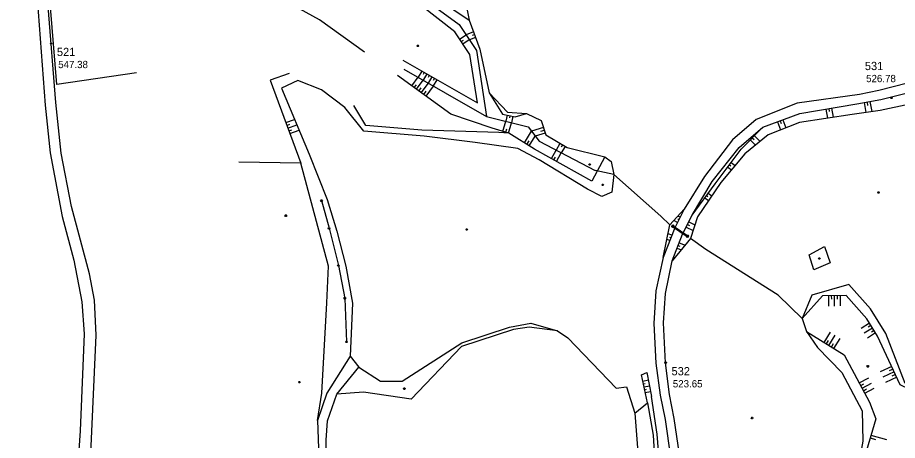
# Model space of a CAD drawing. Extents: x -664960 to -662754, y -993849 to -991145.
# Drawn here: x -664136.9 to -663773.7, y -992233.7 to -992059.4 of the extents above; entities that cross this region are included whole.
import ezdxf

# ---------------------------------------------------------------- set-up
doc = ezdxf.new("R2010")
doc.units = 0
for name, color, linetype in [('Vrstva 1', 7, 'Continuous'), ('Vrstva 12', 7, 'Continuous'), ('Vrstva 13', 7, 'Continuous'), ('Vrstva 24', 7, 'Continuous'), ('Vrstva 27', 7, 'Continuous'), ('Vrstva 28', 7, 'Continuous'), ('Vrstva 63', 7, 'Continuous'), ('Vrstva 8', 7, 'Continuous')]:
    doc.layers.add(name, color=color, linetype=linetype)

msp = doc.modelspace()

# ---------------------------------------------------------------- linework, layer by layer
at = {"layer": 'Vrstva 12'}
msp.add_lwpolyline([(-664087.76, -992082.088), (-664120.622, -992086.914), (-664123.342, -992055.125), (-664091.387, -992050.694)], dxfattribs=at)
at = {"layer": 'Vrstva 13'}
for points in [[(-663971.458, -992070.684), (-663971.278, -992070.984), (-663971.458, -992071.284), (-663971.818, -992071.284), (-663971.998, -992070.984), (-663971.818, -992070.684), (-663971.458, -992070.684)], [(-663900.569, -992119.625), (-663900.389, -992119.925), (-663900.569, -992120.225), (-663900.929, -992120.225), (-663901.109, -992119.925), (-663900.929, -992119.625), (-663900.569, -992119.625)], [(-663895.117, -992127.985), (-663894.937, -992128.285), (-663895.117, -992128.585), (-663895.477, -992128.585), (-663895.657, -992128.285), (-663895.477, -992127.985), (-663895.117, -992127.985)], [(-663781.28, -992131.148), (-663781.1, -992131.448), (-663781.28, -992131.748), (-663781.64, -992131.748), (-663781.82, -992131.448), (-663781.64, -992131.148), (-663781.28, -992131.148)], [(-664025.982, -992140.708), (-664025.802, -992141.008), (-664025.982, -992141.308), (-664026.342, -992141.308), (-664026.522, -992141.008), (-664026.342, -992140.708), (-664025.982, -992140.708)], [(-663951.26, -992146.389), (-663951.08, -992146.689), (-663951.26, -992146.989), (-663951.62, -992146.989), (-663951.8, -992146.689), (-663951.62, -992146.389), (-663951.26, -992146.389)], [(-663785.698, -992202.87), (-663785.518, -992203.17), (-663785.698, -992203.47), (-663786.058, -992203.47), (-663786.238, -992203.17), (-663786.058, -992202.87), (-663785.698, -992202.87)], [(-664020.348, -992209.413), (-664020.168, -992209.713), (-664020.348, -992210.013), (-664020.708, -992210.013), (-664020.888, -992209.713), (-664020.708, -992209.413), (-664020.348, -992209.413)], [(-663833.462, -992224.146), (-663833.282, -992224.446), (-663833.462, -992224.746), (-663833.822, -992224.746), (-663834.002, -992224.446), (-663833.822, -992224.146), (-663833.462, -992224.146)]]:
    msp.add_lwpolyline(points, dxfattribs=at)
at = {"layer": 'Vrstva 24'}
for p, q in [((-663866.501, -992145.522), (-663860.402, -992149.633)), ((-663866.278, -992145.19), (-663860.179, -992149.301))]:
    msp.add_line(p, q, dxfattribs=at)
for points in [[(-663866.185, -992145.374), (-663866.203, -992145.723), (-663866.52, -992145.871), (-663866.818, -992145.67), (-663866.8, -992145.321), (-663866.483, -992145.173), (-663866.185, -992145.374)], [(-663866.129, -992145.507), (-663866.478, -992145.489), (-663866.627, -992145.173), (-663866.427, -992144.874), (-663866.078, -992144.891), (-663865.928, -992145.208), (-663866.129, -992145.507)], [(-663860.086, -992149.484), (-663860.104, -992149.834), (-663860.421, -992149.982), (-663860.719, -992149.781), (-663860.701, -992149.431), (-663860.384, -992149.283), (-663860.086, -992149.484)], [(-663860.328, -992148.984), (-663859.979, -992149.002), (-663859.829, -992149.318), (-663860.03, -992149.617), (-663860.379, -992149.6), (-663860.528, -992149.284), (-663860.328, -992148.984)]]:
    msp.add_lwpolyline(points, dxfattribs=at)
at = {"layer": 'Vrstva 27'}
for points in [[(-664136.56, -991981.24), (-664136.89, -991987.76), (-664134.9, -992004.59), (-664128.78, -992051.29), (-664125.55, -992095.45), (-664123.48, -992115.18), (-664118.48, -992141.38), (-664113.62, -992159.36), (-664110.38, -992176.55), (-664109.39, -992189.71), (-664111.04, -992229.69), (-664113.75, -992269.61), (-664115.45, -992289.53), (-664116.38, -992290.52)], [(-664098.79, -992294.95), (-664110.54, -992286.58), (-664108.77, -992270.34), (-664106.52, -992236.03), (-664104.5, -992190.33), (-664105.14, -992175.85), (-664107.23, -992164.98), (-664114.59, -992137.29), (-664118.86, -992115.21), (-664121.07, -992094.42), (-664124.26, -992054.77), (-664131.31, -991997.85), (-664131.26, -991990.95)], [(-663652.149, -992072.457), (-663666.048, -992064.522), (-663670.915, -992062.515), (-663675.397, -992061.433), (-663685.315, -992060.33), (-663692.602, -992061.892), (-663697.435, -992063.44), (-663712.242, -992070.367), (-663727.163, -992075.883), (-663742.301, -992079.812), (-663757.17, -992083.235), (-663781.317, -992089.372), (-663789.254, -992091.031), (-663815.063, -992094.6), (-663832.035, -992101.429), (-663841.787, -992109.827), (-663853.332, -992124.858), (-663861.753, -992138.392), (-663865.565, -992146.055), (-663870.358, -992158.296), (-663873.442, -992172.032), (-663874.279, -992185.452), (-663873.423, -992201.852), (-663871.565, -992214.969)], [(-663867.768, -992214.752), (-663869.372, -992201.64), (-663870.276, -992185.241), (-663869.416, -992173.115), (-663866.625, -992159.618), (-663862.399, -992148.688), (-663858.277, -992140.51), (-663850.111, -992126.922), (-663839.032, -992112.926), (-663829.283, -992104.516), (-663813.981, -992098.887), (-663790.431, -992094.971), (-663780.543, -992093.142), (-663756.27, -992087.113), (-663743.198, -992083.857), (-663725.949, -992079.492), (-663710.496, -992073.411), (-663696.524, -992067.259), (-663692.016, -992065.833), (-663685.143, -992064.515), (-663675.656, -992065.396), (-663667.253, -992068.6), (-663654.396, -992075.969), (-663648.46, -992078.95)], [(-663999.651, -992198.94), (-664009.165, -992214.188), (-664013.006, -992225.502), (-664012.717, -992236.9)], [(-664009.545, -992233.58), (-664008.923, -992225.678), (-664005.137, -992214.587), (-663996.024, -992203.465)], [(-663927.353, -992297.442), (-663914.548, -992291.55), (-663901.338, -992284.82), (-663883.64, -992275.499), (-663876.185, -992270.406), (-663871.835, -992266.362), (-663867.215, -992259.328), (-663863.972, -992249.911), (-663863.663, -992239.451), (-663865.819, -992224.607), (-663867.768, -992214.752)], [(-663871.565, -992214.969), (-663869.561, -992225.049), (-663867.374, -992240.603), (-663867.883, -992249.281), (-663870.004, -992255.782), (-663872.584, -992260.498), (-663877.958, -992266.124), (-663886.349, -992272.096), (-663902.732, -992281.304), (-663910.857, -992285.368), (-663913.778, -992280.465), (-663916.286, -992268.633)], [(-664009.84, -992299.04), (-664011.01, -992294.41), (-664010.03, -992282.31), (-664009.545, -992233.58)]]:
    msp.add_lwpolyline(points, dxfattribs=at)
at = {"layer": 'Vrstva 28'}
for points in [[(-663981.702, -992044.208), (-663967.289, -992052.977), (-663954.558, -992062.267), (-663947.444, -992072.87), (-663943.265, -992100.123)], [(-663977.412, -992080.619), (-663943.265, -992100.123), (-663926.051, -992104.412), (-663921.605, -992110.368), (-663898.398, -992122.413)]]:
    msp.add_lwpolyline(points, dxfattribs=at)
at = {"layer": 'Vrstva 63'}
for p, q in [((-663954.404, -992068.236), (-663951.757, -992066.443)), ((-663948.61, -992065.291), (-663951.757, -992066.443)), ((-663947.785, -992067.545), (-663950.38, -992068.495)), ((-663948.198, -992066.418), (-663949.154, -992066.768)), ((-663953.731, -992069.229), (-663952.851, -992068.633)), ((-663953.058, -992070.223), (-663950.419, -992068.436)), ((-663970.037, -992081.42), (-663971.508, -992083.991)), ((-663968.996, -992082.016), (-663969.485, -992082.872)), ((-663967.954, -992082.611), (-663969.424, -992085.182)), ((-663974.082, -992087.52), (-663971.508, -992083.991)), ((-663972.144, -992088.934), (-663969.411, -992085.189)), ((-663970.205, -992090.349), (-663967.314, -992086.387)), ((-663966.912, -992083.207), (-663967.402, -992084.063)), ((-663965.87, -992083.803), (-663967.34, -992086.372)), ((-663964.829, -992084.398), (-663965.318, -992085.254)), ((-663963.787, -992084.994), (-663965.256, -992087.562)), ((-663973.113, -992088.227), (-663972.229, -992087.016)), ((-663971.174, -992089.642), (-663970.238, -992088.358)), ((-663969.236, -992091.056), (-663968.246, -992089.701)), ((-663968.266, -992091.764), (-663965.217, -992087.585)), ((-663803.168, -992097.089), (-663802.544, -992100.839)), ((-663801.984, -992096.892), (-663801.775, -992098.147)), ((-663800.8, -992096.695), (-663800.171, -992100.482)), ((-663787.386, -992094.408), (-663786.635, -992098.471)), ((-663786.206, -992094.189), (-663785.953, -992095.557)), ((-663785.026, -992093.971), (-663784.258, -992098.123)), ((-663934.815, -992099.598), (-663935.295, -992102.109)), ((-663933.637, -992099.823), (-663933.801, -992100.681)), ((-663932.458, -992100.048), (-663932.963, -992102.69)), ((-664026.103, -992102.669), (-664022.523, -992101.339)), ((-664025.685, -992103.794), (-664024.478, -992103.345)), ((-664025.267, -992104.919), (-664021.595, -992103.554)), ((-663936.52, -992106.309), (-663935.295, -992102.109)), ((-663934.215, -992106.981), (-663932.964, -992102.689)), ((-663920.737, -992101.848), (-663920.737, -992101.848)), ((-663823.197, -992102.277), (-663821.941, -992105.692)), ((-663822.071, -992101.863), (-663821.657, -992102.99)), ((-663820.945, -992101.449), (-663819.711, -992104.802)), ((-664024.849, -992106.044), (-664023.611, -992105.584)), ((-664024.431, -992107.169), (-664020.667, -992105.77)), ((-663935.368, -992106.645), (-663934.955, -992105.231)), ((-663927.666, -992111.009), (-663924.685, -992106.24)), ((-663919.833, -992104.707), (-663924.685, -992106.24)), ((-663919.11, -992106.996), (-663923.165, -992108.277)), ((-663919.472, -992105.851), (-663920.955, -992106.32)), ((-663832.742, -992108.039), (-663830.329, -992110.409)), ((-663926.648, -992111.645), (-663925.738, -992110.189)), ((-663925.631, -992112.281), (-663923.145, -992108.304)), ((-663912.959, -992111.23), (-663914.588, -992114.009)), ((-663911.924, -992111.837), (-663912.456, -992112.745)), ((-663834.424, -992109.751), (-663832.198, -992111.936)), ((-663833.583, -992108.895), (-663832.811, -992109.653)), ((-663916.519, -992117.487), (-663914.588, -992114.009)), ((-663914.421, -992118.652), (-663912.457, -992115.116)), ((-663910.888, -992112.444), (-663912.455, -992115.117)), ((-663915.47, -992118.069), (-663914.822, -992116.902)), ((-663894.465, -992116.754), (-663899.867, -992126.735)), ((-663842.289, -992119.077), (-663840.641, -992120.309)), ((-663843.726, -992120.999), (-663842.194, -992122.145)), ((-663843.008, -992120.038), (-663842.478, -992120.434)), ((-663853.174, -992133.703), (-663851.679, -992134.806)), ((-663852.461, -992132.737), (-663851.975, -992133.096)), ((-663851.748, -992131.772), (-663850.326, -992132.822)), ((-663864.446, -992143.806), (-663865.956, -992143.055)), ((-663863.912, -992142.732), (-663864.315, -992142.531)), ((-663863.377, -992141.658), (-663864.288, -992141.204)), ((-663859.822, -992143.574), (-663857.29, -992144.85)), ((-663860.902, -992145.717), (-663858.022, -992147.169)), ((-663860.362, -992144.646), (-663859.461, -992145.1)), ((-663867.626, -992151.317), (-663868.81, -992150.853)), ((-663866.751, -992149.082), (-663868.315, -992148.47)), ((-663867.188, -992150.199), (-663867.646, -992150.02)), ((-663864.61, -992154.408), (-663862.873, -992155.079)), ((-663864.178, -992153.288), (-663863.475, -992153.56)), ((-663863.745, -992152.169), (-663861.261, -992153.129)), ((-663802.137, -992174.026), (-663802.107, -992178.339)), ((-663800.937, -992174.017), (-663800.927, -992175.447)), ((-663799.737, -992174.008), (-663799.707, -992178.286)), ((-663798.537, -992174), (-663798.527, -992175.419)), ((-663797.337, -992173.991), (-663797.307, -992178.234)), ((-663785.207, -992185.318), (-663788.678, -992187.494)), ((-663783.932, -992187.351), (-663787.333, -992189.484)), ((-663784.569, -992186.334), (-663785.714, -992187.052)), ((-663803.946, -992193.28), (-663801.345, -992189.093)), ((-663801.907, -992194.546), (-663799.306, -992190.359)), ((-663799.868, -992195.812), (-663797.268, -992191.626)), ((-663782.657, -992189.384), (-663785.989, -992191.473)), ((-663783.295, -992188.368), (-663784.416, -992189.071)), ((-663802.926, -992193.913), (-663802.06, -992192.519)), ((-663800.888, -992195.179), (-663800.022, -992193.785)), ((-663775.98, -992203.244), (-663780.719, -992205.456)), ((-663774.965, -992205.419), (-663779.656, -992207.609)), ((-663775.472, -992204.332), (-663777.042, -992205.064)), ((-663878.742, -992209.255), (-663876.465, -992208.776)), ((-663789.38, -992210.014), (-663785.493, -992207.917)), ((-663773.95, -992207.594), (-663778.594, -992209.761)), ((-663774.457, -992206.506), (-663776.012, -992207.232)), ((-663878.495, -992210.43), (-663877.743, -992210.271)), ((-663878.247, -992211.604), (-663876.009, -992211.132)), ((-663878, -992212.778), (-663877.261, -992212.622)), ((-663877.752, -992213.952), (-663875.553, -992213.489)), ((-663788.81, -992211.07), (-663787.516, -992210.372)), ((-663788.241, -992212.126), (-663784.353, -992210.03)), ((-663787.671, -992213.183), (-663786.377, -992212.484)), ((-663787.101, -992214.239), (-663783.214, -992212.142)), ((-663882.061, -992222.425), (-663878.658, -992265.657)), ((-663784.568, -992231.474), (-663778.117, -992233.347)), ((-663784.903, -992232.627), (-663782.755, -992233.25))]:
    msp.add_line(p, q, dxfattribs=at)
for points in [[(-663993.668, -992073.655), (-664012.262, -992060.304), (-664023.311, -992054.244), (-664037.049, -992039.629), (-664039.796, -992027.226), (-664049.542, -992022.752), (-664056.463, -992015.364), (-664059.529, -992004.564)], [(-663955.63, -992005.604), (-663957.469, -992022.347), (-663952.597, -992049.166), (-663950.399, -992060.402)], [(-663979.157, -992041.523), (-663963.566, -992051.494), (-663950.399, -992060.402), (-663946.03, -992072.343)], [(-663977.818, -992076.971), (-663947.068, -992094.554), (-663950.141, -992074.528), (-663956.408, -992065.276), (-663970.142, -992054.503), (-663985.578, -992045.709)], [(-663687.539, -992071.872), (-663697.594, -992076.22), (-663709.856, -992081.725), (-663728.917, -992088.514), (-663747.464, -992090.007), (-663756.253, -992092.487), (-663780.731, -992097.606), (-663792.314, -992099.303), (-663814.145, -992102.581), (-663827.055, -992107.734), (-663836.598, -992115.531), (-663846.58, -992127.329), (-663856.223, -992141.469), (-663859.063, -992150.47), (-663866.625, -992159.618)], [(-663946.03, -992072.343), (-663942.217, -992090.353), (-663936.677, -992099.242), (-663931.497, -992100.232), (-663926.751, -992098.861), (-663920.737, -992101.848), (-663918.866, -992107.767), (-663910.01, -992112.958), (-663894.465, -992116.754)], [(-664024.779, -992082.397), (-664032.596, -992085.198), (-664019.895, -992119.374)], [(-663894.465, -992116.754), (-663891.768, -992118.673), (-663890.677, -992123.998), (-663891.494, -992131.399), (-663895.643, -992133.171), (-663901.61, -992130.143), (-663921.602, -992117.974), (-663930.359, -992113.334), (-663947.922, -992110.815), (-663968.985, -992108.19), (-663993.917, -992106.174), (-664001.819, -992096.456), (-664011.476, -992089.126), (-664021.244, -992085.345), (-664027.9, -992088.504), (-664016.542, -992115.615), (-664009.033, -992134.368), (-664005.077, -992147.405), (-664001.322, -992161.854), (-663998.58, -992177.108), (-663999.651, -992198.94), (-663996.024, -992203.465), (-663987.09, -992209.303), (-663978.062, -992209.332), (-663953.501, -992193.424), (-663933.858, -992186.937), (-663925.043, -992185.339), (-663913.955, -992188.478), (-663909.694, -992191.348), (-663889.745, -992212.126), (-663885.553, -992211.651), (-663882.061, -992222.425), (-663876.846, -992218.253)], [(-663899.867, -992126.735), (-663923.539, -992113.588), (-663934.02, -992107.038), (-663940.985, -992105.007), (-663958.053, -992099.216), (-663980.014, -992083.191)], [(-663942.217, -992090.353), (-663934.653, -992098.355), (-663926.751, -992098.861)], [(-663756.253, -992092.487), (-663746.828, -992093.758), (-663742.121, -992095.479), (-663732.85, -992101.523), (-663728.116, -992109.932), (-663730.943, -992119.569), (-663737.051, -992129.159), (-663735.83, -992141.172), (-663739.547, -992169.479), (-663745.097, -992181.09), (-663760.244, -992204.525), (-663770.418, -992210.225), (-663778.389, -992189.549), (-663784.771, -992179.426), (-663793.726, -992169.45), (-663808.984, -992173.8), (-663812.912, -992183.474)], [(-663934.02, -992107.038), (-663938.207, -992106.799), (-663970.021, -992105.786), (-663993.154, -992103.789), (-663998.009, -992095.609)], [(-663858.44, -992140.834), (-663848.903, -992127.919), (-663838.16, -992113.557), (-663829.283, -992104.516)], [(-664013.006, -992225.502), (-664011.294, -992214.183), (-664009.163, -992177.028), (-664008.483, -992161.868), (-664019.895, -992119.374), (-664045.484, -992119.035)], [(-663867.558, -992144.831), (-663871.315, -992141.262), (-663890.677, -992123.998), (-663898.398, -992122.413)], [(-664011.244, -992134.52), (-664011.064, -992134.82), (-664011.244, -992135.12), (-664011.604, -992135.12), (-664011.784, -992134.82), (-664011.604, -992134.52), (-664011.244, -992134.52)], [(-664011.424, -992134.82), (-664008.309, -992146.231), (-664004.437, -992161.572), (-664001.801, -992175.118), (-664001.095, -992193.045)], [(-663870.358, -992158.296), (-663867.558, -992144.831), (-663861.753, -992138.392)], [(-664008.129, -992145.931), (-664007.949, -992146.231), (-664008.129, -992146.531), (-664008.489, -992146.531), (-664008.669, -992146.231), (-664008.489, -992145.931), (-664008.129, -992145.931)], [(-663812.912, -992183.474), (-663822.846, -992173.87), (-663852.713, -992154.999), (-663859.063, -992150.47)], [(-663810.137, -992157.214), (-663803.737, -992153.708), (-663801.389, -992160.434), (-663808.185, -992163.354), (-663810.137, -992157.214)], [(-663805.706, -992158.381), (-663805.526, -992158.681), (-663805.706, -992158.981), (-663806.066, -992158.981), (-663806.246, -992158.681), (-663806.066, -992158.381), (-663805.706, -992158.381)], [(-664004.257, -992161.272), (-664004.077, -992161.572), (-664004.257, -992161.872), (-664004.617, -992161.872), (-664004.797, -992161.572), (-664004.617, -992161.272), (-664004.257, -992161.272)], [(-664001.621, -992174.818), (-664001.441, -992175.118), (-664001.621, -992175.418), (-664001.981, -992175.418), (-664002.161, -992175.118), (-664001.981, -992174.818), (-664001.621, -992174.818)], [(-663755.675, -992202.216), (-663768.567, -992212.751), (-663772.484, -992210.734), (-663781.84, -992190.688), (-663786.31, -992183.558), (-663794.872, -992173.974), (-663804.64, -992174.043), (-663812.912, -992183.474)], [(-663812.912, -992183.474), (-663811.128, -992188.818), (-663795.614, -992198.455), (-663785.131, -992217.892), (-663782.629, -992224.795), (-663787.79, -992242.571), (-663783.608, -992264.544), (-663785.134, -992269.708), (-663782.664, -992286.132), (-663788.468, -992301.859), (-663789.894, -992314.506), (-663790.308, -992331.485), (-663793.6, -992345.739), (-663798.571, -992355.807), (-663803.528, -992382.354), (-663806.238, -992402.536), (-663805.007, -992421.537), (-663808.392, -992432.46)], [(-663913.955, -992188.478), (-663925.663, -992186.999), (-663932.123, -992187.962), (-663953.618, -992194.991), (-663974.425, -992216.663), (-663994.042, -992213.855), (-664005.137, -992214.587)], [(-663811.128, -992188.818), (-663806.712, -992195.357), (-663796.642, -992205.688), (-663788.182, -992221.523), (-663787.973, -992234.026), (-663790.612, -992248.321), (-663785.147, -992285.031), (-663788.468, -992301.859)], [(-664000.915, -992192.745), (-664000.735, -992193.045), (-664000.915, -992193.345), (-664001.275, -992193.345), (-664001.455, -992193.045), (-664001.275, -992192.745), (-664000.915, -992192.745)], [(-663876.846, -992218.253), (-663879.279, -992206.708), (-663877.072, -992205.644), (-663875.141, -992215.614)], [(-663977.03, -992212.046), (-663976.85, -992212.346), (-663977.03, -992212.646), (-663977.39, -992212.646), (-663977.57, -992212.346), (-663977.39, -992212.046), (-663977.03, -992212.046)], [(-663876.846, -992218.253), (-663874.498, -992231.493), (-663873.644, -992245.455), (-663872.739, -992255.804), (-663872.51, -992258.26), (-663872.584, -992260.498), (-663871.18, -992256.775), (-663871.792, -992244.873), (-663872.785, -992231.1), (-663875.141, -992215.614)]]:
    msp.add_lwpolyline(points, dxfattribs=at)
at = {"layer": 'Vrstva 8'}
for points in [[(-664122.87, -992069.72), (-664122.69, -992070.02), (-664122.87, -992070.32), (-664123.23, -992070.32), (-664123.41, -992070.02), (-664123.23, -992069.72), (-664122.87, -992069.72)], [(-663775.9, -992092.18), (-663775.72, -992092.48), (-663775.9, -992092.78), (-663776.26, -992092.78), (-663776.44, -992092.48), (-663776.26, -992092.18), (-663775.9, -992092.18)], [(-663869.12, -992201.36), (-663868.94, -992201.66), (-663869.12, -992201.96), (-663869.48, -992201.96), (-663869.66, -992201.66), (-663869.48, -992201.36), (-663869.12, -992201.36)]]:
    msp.add_lwpolyline(points, dxfattribs=at)

# ---------------------------------------------------------------- texts
at = {"layer": 'Vrstva 1'}
for s, p in [('521', (-664120.65, -992075.22)), ('531', (-663787.097, -992081.006)), ('532', (-663866.9, -992206.86))]:
    msp.add_text(s, height=3.4, dxfattribs=at).set_placement(p)
at = {"layer": 'Vrstva 63'}
for s, p in [('547.38', (-664120.126, -992080.2)), ('526.78', (-663786.573, -992085.986)), ('523.65', (-663866.376, -992211.84))]:
    msp.add_text(s, height=3, dxfattribs=at).set_placement(p)

doc.saveas('drawing.dxf')
